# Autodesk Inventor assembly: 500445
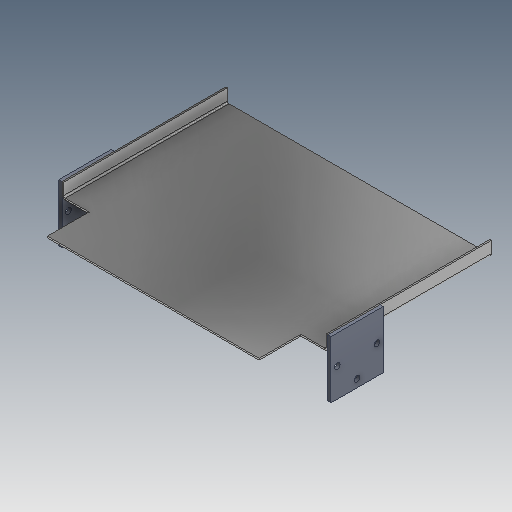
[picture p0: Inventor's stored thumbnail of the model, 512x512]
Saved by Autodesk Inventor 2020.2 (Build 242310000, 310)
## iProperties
Created: 2000-01
Part Number: 500445
Description: WMT-CP,SS,XX,BUCKET_BOTTOM,SLIDING
Document SubType Name: Assembly
Designer: glanglot
Mass: 206.679 g
Surface Area: 1172.01 cm^2
Volume: 93.6904 cm^3
Density: 2.20598 g/cm^3
Control State: 0
Checked Out: False
Master: False
Shininess: 0.0
Length Units: 11269
Angle Units: 11279
Time Units: 11290
Mass Units: 11283
Length Display Precision: 3
Angle Display Precision: 2
Compacted: True
Dimensions: 55x197x260,8 mm
Mass: 0,207 kg
Density: 0.0
Volumn: 0.0
Area: 0.0
PropertySet Name: Model Information
Author: glanglot
Revision Number: -
Title: WMT-CP,SS,XX,BUCKET_BOTTOM,SLIDING
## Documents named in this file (3)
- D:\07 - DEMODATEN\OTX 2019 - Dataset - UPDATE - Dez2019\Designs\07-Packing machine\500445.iam
- D:\07 - DEMODATEN\OTX 2019 - Dataset - UPDATE - Dez2019\Designs\07-Packing machine\Parts\ADSK-011400.ipt
- D:\07 - DEMODATEN\OTX 2019 - Dataset - UPDATE - Dez2019\Designs\07-Packing machine\Parts\ADSK-011404.ipt
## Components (3 placed, 2 different names)
1. ADSK-011400:1 — Fluchtend:6, Passend:3, Passend:4, Fluchtend:7, Fluchtend:10
2. ADSK-011404:1 — Fluchtend:6, Passend:3, Fluchtend:9
3. ADSK-011404:2 — Passend:4, Fluchtend:7, Fluchtend:9, Fluchtend:10
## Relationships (6: Flush 4, Mate 2)
- Fluchtend:6 [Flush]: ADSK-011400:1 ↔ ADSK-011404:1
- Passend:3 [Mate]: ADSK-011400:1 ↔ ADSK-011404:1
- Passend:4 [Mate]: ADSK-011400:1 ↔ ADSK-011404:2
- Fluchtend:7 [Flush]: ADSK-011400:1 ↔ ADSK-011404:2
- Fluchtend:9 [Flush]: ADSK-011404:1 ↔ ADSK-011404:2
- Fluchtend:10 [Flush]: ADSK-011400:1 ↔ ADSK-011404:2
